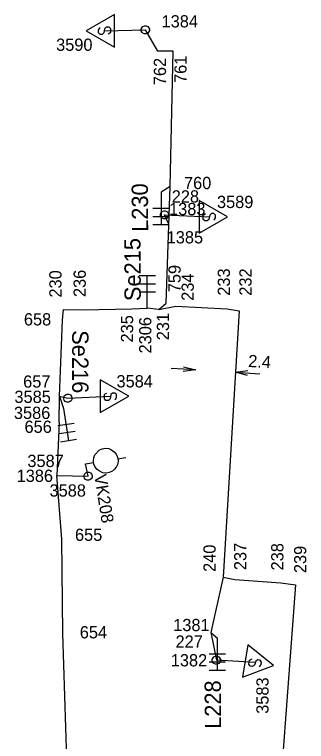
# Model space of a CAD drawing. Extents: x -535557 to -534097, y -1142175 to -1136716.
# Drawn here: x -534533.57 to -534515.67, y -1140560.72 to -1140516.18 of the extents above; entities that cross this region are included whole.
import ezdxf

# ---------------------------------------------------------------- set-up
doc = ezdxf.new("R2010")
doc.units = 0
doc.layers.add('Default', color=7, linetype='Continuous')
doc.layers.add('SS_SZDC', color=7, linetype='Continuous')

# ---------------------------------------------------------------- blocks, each defined once
blk = doc.blocks.new('POINT_DISPLAY')
at = {"layer": 'Default'}
blk.add_line((0, 0), (0, 0), dxfattribs=at)

msp = doc.modelspace()

# ---------------------------------------------------------------- linework, layer by layer
at = {"layer": 'SS_SZDC'}
for p, q in [((-534527.429, -1140516.18), (-534529.179, -1140517.18)), ((-534527.429, -1140518.18), (-534527.429, -1140516.18)), ((-534528.379, -1140517.03), (-534528.429, -1140517.13)), ((-534528.329, -1140516.98), (-534528.379, -1140517.03)), ((-534528.079, -1140517.28), (-534528.029, -1140517.03)), ((-534528.029, -1140517.03), (-534527.929, -1140516.93)), ((-534527.929, -1140516.93), (-534527.779, -1140516.93)), ((-534527.779, -1140516.93), (-534527.679, -1140517.03)), ((-534527.679, -1140517.03), (-534527.679, -1140517.28)), ((-534525.8, -1140517.071), (-534525.75, -1140516.971)), ((-534525.799, -1140517.171), (-534525.8, -1140517.071)), ((-534525.75, -1140516.971), (-534525.701, -1140516.92)), ((-534525.701, -1140516.92), (-534525.601, -1140516.87)), ((-534525.601, -1140516.87), (-534525.501, -1140516.869)), ((-534525.501, -1140516.869), (-534525.401, -1140516.919)), ((-534525.401, -1140516.919), (-534525.35, -1140516.968)), ((-534525.35, -1140516.968), (-534525.3, -1140517.068)), ((-534525.3, -1140517.068), (-534525.299, -1140517.168)), ((-534529.179, -1140517.18), (-534527.429, -1140518.18)), ((-534528.429, -1140517.13), (-534528.429, -1140517.28)), ((-534528.429, -1140517.28), (-534528.329, -1140517.38)), ((-534528.329, -1140517.38), (-534528.179, -1140517.38)), ((-534528.179, -1140517.38), (-534528.079, -1140517.28)), ((-534528.029, -1140517.18), (-534525.55, -1140517.12)), ((-534527.729, -1140517.33), (-534527.829, -1140517.38)), ((-534527.679, -1140517.28), (-534527.729, -1140517.33)), ((-534525.749, -1140517.271), (-534525.799, -1140517.171)), ((-534525.698, -1140517.32), (-534525.749, -1140517.271)), ((-534525.598, -1140517.37), (-534525.698, -1140517.32)), ((-534525.498, -1140517.369), (-534525.598, -1140517.37)), ((-534525.55, -1140517.12), (-534524.81, -1140518.42)), ((-534525.398, -1140517.319), (-534525.498, -1140517.369)), ((-534525.349, -1140517.268), (-534525.398, -1140517.319)), ((-534525.299, -1140517.168), (-534525.349, -1140517.268)), ((-534523.84, -1140518.43), (-534524.81, -1140518.42)), ((-534524.02, -1140526.719), (-534523.84, -1140518.43)), ((-534524.02, -1140526.719), (-534524.579, -1140527.069)), ((-534524.26, -1140533.86), (-534524.02, -1140526.719)), ((-534524.579, -1140527.069), (-534524.579, -1140529.069)), ((-534522.249, -1140527.579), (-534522.249, -1140529.579)), ((-534520.499, -1140528.579), (-534522.249, -1140527.579)), ((-534524.079, -1140528.069), (-534525.079, -1140528.069)), ((-534524.521, -1140528.25), (-534524.421, -1140528.2)), ((-534524.421, -1140528.2), (-534524.321, -1140528.199)), ((-534524.321, -1140528.199), (-534524.221, -1140528.249)), ((-534524.079, -1140528.569), (-534525.079, -1140528.569)), ((-534524.62, -1140528.401), (-534524.57, -1140528.301)), ((-534524.619, -1140528.501), (-534524.62, -1140528.401)), ((-534524.569, -1140528.601), (-534524.619, -1140528.501)), ((-534524.57, -1140528.301), (-534524.521, -1140528.25)), ((-534524.518, -1140528.65), (-534524.569, -1140528.601)), ((-534524.418, -1140528.7), (-534524.518, -1140528.65)), ((-534524.109, -1140529.03), (-534524.369, -1140528.45)), ((-534524.369, -1140528.45), (-534521.649, -1140528.579)), ((-534524.218, -1140528.649), (-534524.318, -1140528.699)), ((-534524.221, -1140528.249), (-534524.17, -1140528.298)), ((-534524.169, -1140528.598), (-534524.218, -1140528.649)), ((-534524.17, -1140528.298), (-534524.12, -1140528.398)), ((-534524.119, -1140528.498), (-534524.169, -1140528.598)), ((-534524.12, -1140528.398), (-534524.119, -1140528.498)), ((-534522.249, -1140529.579), (-534520.499, -1140528.579)), ((-534521.999, -1140528.479), (-534521.949, -1140528.429)), ((-534521.999, -1140528.729), (-534521.999, -1140528.479)), ((-534521.949, -1140528.429), (-534521.849, -1140528.379)), ((-534521.599, -1140528.479), (-534521.649, -1140528.729)), ((-534521.499, -1140528.379), (-534521.599, -1140528.479)), ((-534521.349, -1140528.379), (-534521.499, -1140528.379)), ((-534521.249, -1140528.479), (-534521.349, -1140528.379)), ((-534521.299, -1140528.729), (-534521.249, -1140528.629)), ((-534521.249, -1140528.629), (-534521.249, -1140528.479)), ((-534524.079, -1140529.069), (-534525.079, -1140529.069)), ((-534524.318, -1140528.699), (-534524.418, -1140528.7)), ((-534521.899, -1140528.829), (-534521.999, -1140528.729)), ((-534521.749, -1140528.829), (-534521.899, -1140528.829)), ((-534521.649, -1140528.729), (-534521.749, -1140528.829)), ((-534521.349, -1140528.779), (-534521.299, -1140528.729)), ((-534525.93, -1140532.17), (-534524.93, -1140532.17)), ((-534525.43, -1140534.17), (-534525.43, -1140532.17)), ((-534525.93, -1140532.67), (-534524.93, -1140532.67)), ((-534525.93, -1140533.17), (-534524.93, -1140533.17)), ((-534524.71, -1140534.26), (-534524.26, -1140533.86)), ((-534530.63, -1140534.899), (-534530.56, -1140534.25)), ((-534530.56, -1140534.25), (-534529.39, -1140534.28)), ((-534529.39, -1140534.28), (-534526.38, -1140534.219)), ((-534526.38, -1140534.219), (-534525.43, -1140534.17)), ((-534524.71, -1140534.26), (-534525.43, -1140534.17)), ((-534524.71, -1140534.26), (-534523.68, -1140534.049)), ((-534523.68, -1140534.049), (-534520.52, -1140534.209)), ((-534519.8, -1140534.329), (-534520.779, -1140550.659)), ((-534520.52, -1140534.209), (-534519.8, -1140534.329)), ((-534530.81, -1140539.569), (-534530.63, -1140534.899)), ((-534522.46, -1140537.954), (-534523.957, -1140537.865)), ((-534522.46, -1140537.954), (-534523.217, -1140538.059)), ((-534523.199, -1140537.76), (-534522.46, -1140537.954)), ((-534520.026, -1140538.1), (-534519.268, -1140537.996)), ((-534520.026, -1140538.1), (-534518.528, -1140538.19)), ((-534519.286, -1140538.295), (-534520.026, -1140538.1)), ((-534528.31, -1140538.569), (-534528.31, -1140540.569)), ((-534526.56, -1140539.569), (-534528.31, -1140538.569)), ((-534528.01, -1140539.419), (-534527.91, -1140539.369)), ((-534527.56, -1140539.369), (-534527.66, -1140539.469)), ((-534527.41, -1140539.369), (-534527.56, -1140539.369)), ((-534527.31, -1140539.469), (-534527.41, -1140539.369)), ((-534530.84, -1140541.18), (-534530.81, -1140539.569)), ((-534530.81, -1140539.569), (-534530.3, -1140539.69)), ((-534530.81, -1140539.569), (-534530.569, -1140540.319)), ((-534530.546, -1140539.732), (-534530.545, -1140539.621)), ((-534530.524, -1140539.8), (-534530.546, -1140539.732)), ((-534530.545, -1140539.621), (-534530.5, -1140539.531)), ((-534530.458, -1140539.89), (-534530.524, -1140539.8)), ((-534530.5, -1140539.531), (-534530.41, -1140539.465)), ((-534530.41, -1140539.465), (-534530.342, -1140539.443)), ((-534530.342, -1140539.443), (-534530.231, -1140539.444)), ((-534530.3, -1140539.69), (-534527.71, -1140539.569)), ((-534530.231, -1140539.444), (-534530.141, -1140539.489)), ((-534530.141, -1140539.489), (-534530.075, -1140539.579)), ((-534530.054, -1140539.758), (-534530.099, -1140539.848)), ((-534530.075, -1140539.579), (-534530.053, -1140539.647)), ((-534530.053, -1140539.647), (-534530.054, -1140539.758)), ((-534528.31, -1140540.569), (-534526.56, -1140539.569)), ((-534528.06, -1140539.469), (-534528.01, -1140539.419)), ((-534528.06, -1140539.719), (-534528.06, -1140539.469)), ((-534527.96, -1140539.819), (-534528.06, -1140539.719)), ((-534527.81, -1140539.819), (-534527.96, -1140539.819)), ((-534527.71, -1140539.719), (-534527.81, -1140539.819)), ((-534527.66, -1140539.469), (-534527.71, -1140539.719)), ((-534527.41, -1140539.769), (-534527.36, -1140539.719)), ((-534527.36, -1140539.719), (-534527.31, -1140539.619)), ((-534527.31, -1140539.619), (-534527.31, -1140539.469)), ((-534530.368, -1140539.935), (-534530.458, -1140539.89)), ((-534530.257, -1140539.936), (-534530.368, -1140539.935)), ((-534530.189, -1140539.914), (-534530.257, -1140539.936)), ((-534530.099, -1140539.848), (-534530.189, -1140539.914)), ((-534530.569, -1140540.319), (-534530.257, -1140542.295)), ((-534530.84, -1140541.18), (-534530.97, -1140544.42)), ((-534529.919, -1140541.229), (-534530.907, -1140541.385)), ((-534529.841, -1140541.723), (-534530.829, -1140541.879)), ((-534529.763, -1140542.217), (-534530.75, -1140542.373)), ((-534528.638, -1140543.163), (-534528.381, -1140542.87)), ((-534528.381, -1140542.87), (-534528.191, -1140542.789)), ((-534528.191, -1140542.789), (-534527.993, -1140542.758)), ((-534527.993, -1140542.758), (-534527.788, -1140542.776)), ((-534527.788, -1140542.776), (-534527.624, -1140542.851)), ((-534527.624, -1140542.851), (-534527.453, -1140542.976)), ((-534528.731, -1140543.533), (-534528.713, -1140543.327)), ((-534528.713, -1140543.327), (-534528.638, -1140543.163)), ((-534527.453, -1140542.976), (-534527.33, -1140543.108)), ((-534527.33, -1140543.108), (-534527.25, -1140543.298)), ((-534527.25, -1140543.298), (-534527.218, -1140543.495)), ((-534527.234, -1140543.397), (-534526.74, -1140543.318)), ((-534529.21, -1140543.709), (-534528.716, -1140543.631)), ((-534529.06, -1140544.469), (-534529.21, -1140543.709)), ((-534528.716, -1140543.631), (-534528.731, -1140543.533)), ((-534528.7, -1140543.73), (-534528.716, -1140543.631)), ((-534528.619, -1140543.92), (-534528.7, -1140543.73)), ((-534527.237, -1140543.701), (-534527.312, -1140543.865)), ((-534527.218, -1140543.495), (-534527.237, -1140543.701)), ((-534529.26, -1140544.311), (-534529.17, -1140544.245)), ((-534529.17, -1140544.245), (-534529.102, -1140544.223)), ((-534529.102, -1140544.223), (-534528.991, -1140544.224)), ((-534528.991, -1140544.224), (-534528.901, -1140544.269)), ((-534528.901, -1140544.269), (-534528.835, -1140544.359)), ((-534528.497, -1140544.052), (-534528.619, -1140543.92)), ((-534528.325, -1140544.177), (-534528.497, -1140544.052)), ((-534528.162, -1140544.252), (-534528.325, -1140544.177)), ((-534527.956, -1140544.27), (-534528.162, -1140544.252)), ((-534527.759, -1140544.239), (-534527.956, -1140544.27)), ((-534527.569, -1140544.158), (-534527.759, -1140544.239)), ((-534527.437, -1140544.036), (-534527.569, -1140544.158)), ((-534527.312, -1140543.865), (-534527.437, -1140544.036)), ((-534530.659, -1140548.329), (-534530.97, -1140544.42)), ((-534530.97, -1140544.42), (-534529.06, -1140544.469)), ((-534529.306, -1140544.512), (-534529.305, -1140544.401)), ((-534529.284, -1140544.58), (-534529.306, -1140544.512)), ((-534529.305, -1140544.401), (-534529.26, -1140544.311)), ((-534529.218, -1140544.67), (-534529.284, -1140544.58)), ((-534529.128, -1140544.715), (-534529.218, -1140544.67)), ((-534529.017, -1140544.716), (-534529.128, -1140544.715)), ((-534528.949, -1140544.694), (-534529.017, -1140544.716)), ((-534528.859, -1140544.628), (-534528.949, -1140544.694)), ((-534528.814, -1140544.538), (-534528.859, -1140544.628)), ((-534528.835, -1140544.359), (-534528.813, -1140544.427)), ((-534528.813, -1140544.427), (-534528.814, -1140544.538)), ((-534530.6, -1140554.11), (-534530.659, -1140548.329)), ((-534520.779, -1140550.659), (-534521.529, -1140554.049)), ((-534520.779, -1140550.659), (-534520.069, -1140550.799)), ((-534520.069, -1140550.799), (-534517.229, -1140550.989)), ((-534517.229, -1140550.989), (-534516.34, -1140551.12)), ((-534516.34, -1140551.12), (-534517.22, -1140562.84)), ((-534521.529, -1140554.049), (-534521.14, -1140554.37)), ((-534521.529, -1140554.049), (-534521.189, -1140555.739)), ((-534530.3, -1140563.709), (-534530.6, -1140554.11)), ((-534521.14, -1140554.37), (-534521.14, -1140556.37)), ((-534519.266, -1140554.808), (-534519.579, -1140556.783)), ((-534517.694, -1140556.069), (-534519.266, -1140554.808)), ((-534520.64, -1140555.37), (-534521.64, -1140555.37)), ((-534521.44, -1140555.691), (-534521.39, -1140555.591)), ((-534521.439, -1140555.791), (-534521.44, -1140555.691)), ((-534521.389, -1140555.891), (-534521.439, -1140555.791)), ((-534521.39, -1140555.591), (-534521.341, -1140555.54)), ((-534521.341, -1140555.54), (-534521.241, -1140555.49)), ((-534521.241, -1140555.49), (-534521.141, -1140555.489)), ((-534518.829, -1140555.889), (-534521.189, -1140555.739)), ((-534521.141, -1140555.489), (-534521.041, -1140555.539)), ((-534521.041, -1140555.539), (-534520.99, -1140555.588)), ((-534520.99, -1140555.588), (-534520.94, -1140555.688)), ((-534520.939, -1140555.788), (-534520.989, -1140555.888)), ((-534520.94, -1140555.688), (-534520.939, -1140555.788)), ((-534519.199, -1140555.983), (-534519.16, -1140555.736)), ((-534519.16, -1140555.736), (-534519.102, -1140555.694)), ((-534519.102, -1140555.694), (-534518.996, -1140555.661)), ((-534518.764, -1140555.799), (-534518.853, -1140556.038)), ((-534518.65, -1140555.715), (-534518.764, -1140555.799)), ((-534518.502, -1140555.739), (-534518.65, -1140555.715)), ((-534518.419, -1140555.853), (-534518.502, -1140555.739)), ((-534518.442, -1140556.001), (-534518.419, -1140555.853)), ((-534520.64, -1140555.87), (-534521.64, -1140555.87)), ((-534521.338, -1140555.94), (-534521.389, -1140555.891)), ((-534521.238, -1140555.99), (-534521.338, -1140555.94)), ((-534521.138, -1140555.989), (-534521.238, -1140555.99)), ((-534521.038, -1140555.939), (-534521.138, -1140555.989)), ((-534520.989, -1140555.888), (-534521.038, -1140555.939)), ((-534519.579, -1140556.783), (-534517.694, -1140556.069)), ((-534519.116, -1140556.097), (-534519.199, -1140555.983)), ((-534518.967, -1140556.121), (-534519.116, -1140556.097)), ((-534518.853, -1140556.038), (-534518.967, -1140556.121)), ((-534518.564, -1140556.134), (-534518.507, -1140556.092)), ((-534518.507, -1140556.092), (-534518.442, -1140556.001)), ((-534520.64, -1140556.37), (-534521.64, -1140556.37))]:
    msp.add_line(p, q, dxfattribs=at)

# ---------------------------------------------------------------- block references
for p in [(-534528.029, -1140517.18), (-534525.55, -1140517.12), (-534525.55, -1140517.12), (-534524.81, -1140518.42), (-534523.84, -1140518.43), (-534524.02, -1140526.719), (-534524.579, -1140527.069), (-534524.369, -1140528.45), (-534524.369, -1140528.45), (-534521.649, -1140528.579), (-534524.109, -1140529.03), (-534524.26, -1140533.86), (-534530.56, -1140534.25), (-534529.39, -1140534.28), (-534526.38, -1140534.219), (-534525.43, -1140534.17), (-534524.71, -1140534.26), (-534523.68, -1140534.049), (-534520.52, -1140534.209), (-534519.8, -1140534.329), (-534530.63, -1140534.899), (-534530.81, -1140539.569), (-534530.3, -1140539.69), (-534530.3, -1140539.69), (-534527.71, -1140539.569), (-534530.569, -1140540.319), (-534530.84, -1140541.18), (-534529.21, -1140543.709), (-534530.97, -1140544.42), (-534529.06, -1140544.469), (-534529.06, -1140544.469), (-534530.659, -1140548.329), (-534520.779, -1140550.659), (-534520.069, -1140550.799), (-534517.229, -1140550.989), (-534516.34, -1140551.12), (-534521.529, -1140554.049), (-534530.6, -1140554.11), (-534521.14, -1140554.37), (-534521.189, -1140555.739), (-534521.189, -1140555.739), (-534518.829, -1140555.889)]:
    msp.add_blockref('POINT_DISPLAY', p, dxfattribs=at)

# ---------------------------------------------------------------- texts
for s, p in [('1384', (-534524.55, -1140516.97)), ('3590', (-534531.017, -1140518.404)), ('760', (-534523.176, -1140526.875)), ('228', (-534523.927, -1140527.699)), ('3589', (-534521.153, -1140528.036)), ('1383', (-534524.09, -1140528.471)), ('1385', (-534524.237, -1140530.203)), ('658', (-534532.992, -1140535.229)), ('657', (-534533.038, -1140539.041)), ('3584', (-534527.315, -1140539.025)), ('3585', (-534533.572, -1140539.976)), ('3586', (-534533.605, -1140540.96)), ('656', (-534532.955, -1140541.811)), ('3587', (-534532.779, -1140543.904)), ('1386', (-534533.438, -1140544.814)), ('3588', (-534531.42, -1140545.715)), ('655', (-534529.859, -1140548.43)), ('1381', (-534523.837, -1140553.959)), ('654', (-534529.566, -1140554.402)), ('227', (-534523.695, -1140554.973)), ('1382', (-534523.987, -1140556.118))]:
    msp.add_text(s, height=0.75, dxfattribs=at).set_placement(p)
for s, height, rotation, p in [('762', 0.75, 90, (-534524.278, -1140520.509)), ('761', 0.75, 90, (-534523.017, -1140520.372)), ('L230', 1, 90.3757, (-534525.37, -1140529.493)), ('Se215', 1, 90.3757, (-534525.819, -1140533.737)), ('759', 0.75, 90, (-534523.38, -1140533.195)), ('233', 0.75, 90, (-534520.36, -1140533.407)), ('232', 0.75, 90, (-534519.033, -1140533.406)), ('230', 0.75, 90, (-534530.685, -1140533.522)), ('236', 0.75, 90, (-534529.199, -1140533.491)), ('234', 0.75, 90, (-534522.577, -1140533.718)), ('235', 0.75, 90, (-534526.293, -1140536.273)), ('2306', 0.75, 90, (-534525.178, -1140536.945)), ('231', 0.75, 90, (-534524.093, -1140536.136)), ('Se216', 1, 270, (-534530.034, -1140535.521)), ('2.4', 0.75, 356.5657, (-534519.255, -1140537.771)), ('VK208', 0.75, 279, (-534528.682, -1140544.407)), ('240', 0.75, 90, (-534521.234, -1140550.331)), ('237', 0.75, 90, (-534519.351, -1140550.22)), ('238', 0.75, 90, (-534517.08, -1140550.239)), ('239', 0.75, 90, (-534515.677, -1140550.405)), ('L228', 1, 90.3757, (-534520.896, -1140559.945)), ('3583', 0.75, 90, (-534517.991, -1140559.024))]:
    msp.add_text(s, height=height, rotation=rotation, dxfattribs=at).set_placement(p)

doc.saveas('drawing.dxf')
